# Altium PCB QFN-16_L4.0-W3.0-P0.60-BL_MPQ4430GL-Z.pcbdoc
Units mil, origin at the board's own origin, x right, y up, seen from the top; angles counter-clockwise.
Board outline 680 x 665 mil, 2 copper layers (Top Layer, Bottom Layer), stack 2.757 mil thick; 1 components, 0 nets, 16 pads, 0 vias.
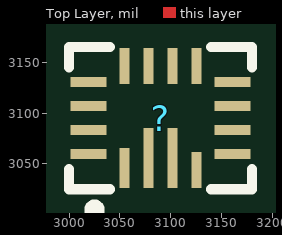
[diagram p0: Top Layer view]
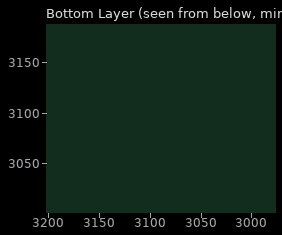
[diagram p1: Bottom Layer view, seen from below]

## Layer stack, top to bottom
Top Solder Mask Layer: solder mask 0.394, Dk 3.3
Top Layer: signal copper 1.379
Bottom Layer: signal copper 1.378
Bottom Solder Mask Layer: solder mask 0.394, Dk 3.3

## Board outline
3430,2750 2750,2750 2750,3415 3430,3415

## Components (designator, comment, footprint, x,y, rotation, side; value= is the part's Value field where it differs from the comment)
? "QFN-16_L4.0-W3.0-P0.60-BL_MPQ4430GL-Z" QFN-16_L4.0-W3.0-P0.60-BL_MPQ4430GL-Z 3090,3095 r0 top

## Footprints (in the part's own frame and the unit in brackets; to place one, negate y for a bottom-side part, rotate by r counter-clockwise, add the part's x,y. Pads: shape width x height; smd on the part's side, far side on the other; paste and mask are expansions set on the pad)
QFN-16_L4.0-W3.0-P0.60-BL_MPQ4430GL-Z [mm]
  rect 0.25x1 smd paste+0 mask+0.051: 1(-0.9,-1.25)
  rect 0.25x1.5 smd paste+0 mask+0.051: 2(-0.3,-1) 3(0.3,-1)
  rect 0.25x0.9 smd paste+0 mask+0.051: 4(0.9,-1.3) 9(0.9,1.3) 10(0.3,1.3) 11(-0.3,1.3) 12(-0.9,1.3)
  rect 0.9x0.25 smd paste+0 mask+0.051: 5(1.8,-0.9) 6(1.8,-0.3) 7(1.8,0.3) 8(1.8,0.9) 13(-1.8,0.9) 14(-1.8,0.3) 15(-1.8,-0.3) 16(-1.8,-0.9)
  silkscreen extent -2.29,-2.41 2.29,1.78

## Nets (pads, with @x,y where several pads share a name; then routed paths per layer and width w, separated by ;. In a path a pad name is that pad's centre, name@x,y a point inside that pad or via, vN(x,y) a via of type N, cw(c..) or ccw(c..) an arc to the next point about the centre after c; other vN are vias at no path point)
pads on no net: ?.1 ?.2 ?.3 ?.4 ?.5 ?.6 ?.7 ?.8 ?.9 ?.10 ?.11 ?.12 ?.13 ?.14 ?.15 ?.16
